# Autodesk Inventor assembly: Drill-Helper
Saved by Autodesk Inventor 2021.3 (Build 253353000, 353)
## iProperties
Created: 2023-07
Part Number: Drill-Helper
Document SubType Name: Assembly
Designer: AdminForWorker
Title: Drill-Helper v2
Author: AdminForWorker
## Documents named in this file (2)
- c:\worker\convert-fusion-r03-cosv3\tmp\job-1\7\output\files\ed1a9385-d3ff-40e3-bd37-0ed800457cac\2e158b46-6d21-4d21-bc7b-1e92a28e356c.iam
- c:\worker\convert-fusion-r03-cosv3\tmp\job-1\7\output\files\ed1a9385-d3ff-40e3-bd37-0ed800457cac\Drill-Guide-Gland-Hole v2.iam
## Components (1 placed, 1 different names)
1. Drill-Guide-Gland-Hole v2:1 [sub-assembly]
